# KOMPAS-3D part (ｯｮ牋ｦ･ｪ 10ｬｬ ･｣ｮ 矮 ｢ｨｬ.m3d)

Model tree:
1. Эскиз:1
2. Операция выдавливания:1
     Расстояние 1 = 8
3. Эскиз:2
4. Операция выдавливания:2
     Расстояние 1 = 1
5. Эскиз:3
6. Операция выдавливания:3
     Расстояние 1 = 2.5; Угол 1 = 8
7. Эскиз:4
8. Вырезать элемент выдавливания:1
     Расстояние 1 = 20
9. Эскиз:5
10. Вырезать элемент выдавливания:2
     Расстояние 1 = 3; Угол 1 = 19
11. Скругление:1
     Радиус = 1
12. Скругление:2
     Радиус = 1
13. Скругление:3
     Радиус = 1
14. Эскиз:6
15. Эскиз:7
16. Вырезать элемент выдавливания:3
     Расстояние 2 = 30; Расстояние 1 = 60
17. Эскиз:8
18. Вырезать элемент выдавливания:4
     Расстояние 2 = 30; Расстояние 1 = 60
19. Эскиз:9
20. Операция выдавливания:4
     Расстояние 1 = 10; Расстояние 2 = 62
21. Эскиз:10
22. Вырезать элемент выдавливания:5
     Расстояние 2 = 30; Расстояние 1 = 60
23. Скругление:4
     Радиус = 2
24. Скругление:5
     Радиус = 2
25. Эскиз:11
26. Вырезать элемент выдавливания:6
     Расстояние 1 = 10
27. Эскиз:12
28. Вырезать элемент выдавливания:7
     Расстояние 1 = 2.5
29. Эскиз:13
30. Вырезать элемент выдавливания:8
     Расстояние 2 = 40; Расстояние 1 = 30
31. Эскиз:14
32. Операция выдавливания:5
     Расстояние 1 = 10
33. Операция выдавливания:6
     Расстояние 1 = 2.5; Расстояние 2 = 5.94316
34. Эскиз:15
35. Вырезать элемент выдавливания:9
     Расстояние 1 = 20
36. Скругление:6
     Радиус = 1
37. Скругление:7
     Радиус = 1
38. Операция выдавливания:7
     Расстояние 1 = 2
